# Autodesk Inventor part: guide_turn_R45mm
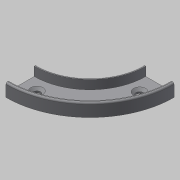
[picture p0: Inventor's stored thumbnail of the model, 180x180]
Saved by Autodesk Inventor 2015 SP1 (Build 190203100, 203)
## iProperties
Created: 2015-06
Part Number: guide_turn_R45mm
Material: Generic
Document SubType Name: Modeling
Designer: uidn2323
Density: 1 g/cm^3
Appearance: Default
Author: uidn2323
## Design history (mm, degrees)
derived "lyžina_R4.5.ipt"
  sketch "Sketch1"
    geometry: L1 (5, -1)-(-14, -1) reference; L2 (-14, -1)-(-14, 6) reference; L3 (5, 6)-(5, -1) reference; L4 (3.5, 1.5)-(-12.5, 1.5) reference; L5 (-12.5, 1.5)-(-12.5, 7) reference; L6 (3.5, 7)-(3.5, 1.5) reference; L7 (-13, 7)-(-12.5, 7) reference; L8 (3.5, 7)-(4, 7) reference; A1 r 1 centre (4, 6) between (5, 6) and (4, 7) reference; A2 r 1 centre (-13, 6) between (-13, 7) and (-14, 6) reference; 4 further points
  sketch "Sketch2"
    geometry: L1 (-38, -46.689)-(-38, 0) reference; L2 (-38, 0)-(16.098, 0) reference; A1 r 45 centre (-38, 0) between (-38, -45) and (7, 0) reference; 1 further point
  sketch "Sketch3"
    geometry: C1 r 2.25 at (-6.327, 10.13) reference; C2 r 2.25 at (25.895, 41.499) reference; 1 further point
feature "Solid1::lyžina_R4.5.ipt"
tag "TaggingFeature1"
body "Solid1"
